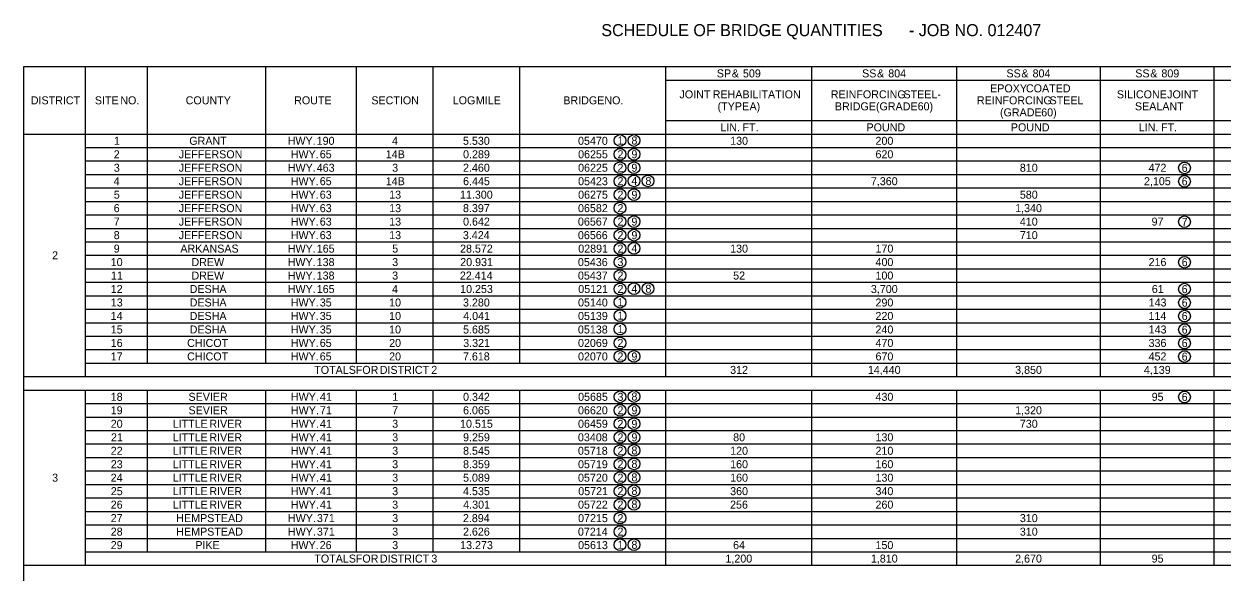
# Model space of a CAD drawing. Extents: x 16 to 1228740, y 11 to 152440.
# Drawn here: x 15.863 to 17.42, y 11.685 to 12.397 of the extents above; entities that cross this region are included whole.
import ezdxf

# ---------------------------------------------------------------- set-up
doc = ezdxf.new("R2010")
doc.units = 0
doc.layers.add('B_Text', color=7, linetype='Continuous')
doc.layers.add('Default', color=7, linetype='Continuous')

msp = doc.modelspace()

# ---------------------------------------------------------------- linework, layer by layer
at = {"layer": 'B_Text'}
msp.add_line((15.8634, 12.342), (15.8634, 12.342), dxfattribs=at)
for centre in [(16.6381, 12.246), (16.6563, 12.246), (16.6381, 12.2281), (16.6563, 12.2281), (16.6381, 12.2106), (16.6563, 12.2106), (17.3717, 12.2104), (16.6381, 12.1931), (16.6563, 12.1935), (16.6744, 12.1935), (17.3717, 12.1929), (16.6381, 12.1756), (16.6563, 12.1756), (16.6381, 12.1581), (16.6381, 12.1406), (16.6563, 12.1406), (17.3717, 12.1404), (16.6381, 12.123), (16.6563, 12.123), (16.6381, 12.1055), (16.6563, 12.1059), (16.6381, 12.088), (17.3717, 12.0878), (16.6381, 12.0705), (16.6381, 12.053), (16.6563, 12.0534), (16.6744, 12.0534), (17.3717, 12.0528), (16.6381, 12.0359), (17.3717, 12.0353), (16.6381, 12.0184), (17.3717, 12.0178), (16.6381, 12.0009), (17.3717, 12.0002), (16.6381, 11.9829), (17.3717, 11.9827), (16.6381, 11.9654), (16.6563, 11.9654), (17.3717, 11.9652), (16.6381, 11.9129), (16.6563, 11.9133), (17.3717, 11.9127), (16.6381, 11.8954), (16.6563, 11.8954), (16.6381, 11.8779), (16.6563, 11.8779), (16.6381, 11.8603), (16.6563, 11.8603), (16.6381, 11.8428), (16.6563, 11.8432), (16.6381, 11.8253), (16.6563, 11.8257), (16.6381, 11.8078), (16.6563, 11.8082), (16.6381, 11.7903), (16.6563, 11.7907), (16.6381, 11.7728), (16.6563, 11.7732), (16.6381, 11.7553), (16.6381, 11.7377), (16.6381, 11.7206), (16.6563, 11.7206)]:
    msp.add_circle(centre, 0.00762, dxfattribs=at)
at = {"layer": 'Default'}
for p, q in [((15.8634, 12.342), (17.9605, 12.342)), ((15.8634, 11.2211), (15.8634, 12.342)), ((15.9436, 11.9391), (15.9436, 12.342)), ((16.0238, 11.9567), (16.0238, 12.342)), ((16.1778, 11.9567), (16.1778, 12.342)), ((16.2958, 11.9567), (16.2958, 12.342)), ((16.3953, 11.9567), (16.3953, 12.342)), ((16.5078, 11.9567), (16.5078, 12.342)), ((16.6976, 11.9391), (16.6976, 12.342)), ((16.8875, 11.9391), (16.8875, 12.342)), ((17.0756, 11.9391), (17.0756, 12.342)), ((17.2627, 11.9391), (17.2627, 12.342)), ((17.4102, 11.9391), (17.4102, 12.342)), ((16.6976, 12.3244), (17.9605, 12.3244)), ((16.6976, 12.2719), (17.9605, 12.2719)), ((15.8634, 12.2544), (17.9605, 12.2544)), ((17.4102, 12.1668), (17.4102, 12.2544)), ((15.9436, 12.2369), (17.9605, 12.2369)), ((15.9436, 12.2194), (17.9605, 12.2194)), ((15.9436, 12.2019), (17.9605, 12.2019)), ((15.9436, 12.1843), (17.9605, 12.1843)), ((15.9436, 12.1668), (17.9605, 12.1668)), ((15.9436, 12.1493), (17.9605, 12.1493)), ((15.9436, 12.1318), (17.9605, 12.1318)), ((15.9436, 12.1143), (17.9605, 12.1143)), ((15.9436, 12.0968), (17.9605, 12.0968)), ((15.9436, 12.0793), (17.9605, 12.0793)), ((15.9436, 12.0617), (17.9605, 12.0617)), ((15.9436, 12.0442), (17.9605, 12.0442)), ((15.9436, 12.0267), (17.9605, 12.0267)), ((15.9436, 12.0092), (17.9605, 12.0092)), ((15.9436, 11.9917), (17.9605, 11.9917)), ((15.9436, 11.9742), (17.9605, 11.9742)), ((17.4102, 11.9567), (17.4102, 11.9742)), ((15.9436, 11.9567), (17.9605, 11.9567)), ((15.8634, 11.9391), (17.9605, 11.9391)), ((15.8634, 11.9216), (17.9605, 11.9216)), ((15.9436, 11.694), (15.9436, 11.9216)), ((16.0238, 11.7115), (16.0238, 11.9216)), ((16.1778, 11.7115), (16.1778, 11.9216)), ((16.2958, 11.7115), (16.2958, 11.9216)), ((16.3953, 11.7115), (16.3953, 11.9216)), ((16.5078, 11.7115), (16.5078, 11.9216)), ((16.6976, 11.694), (16.6976, 11.9216)), ((16.8875, 11.694), (16.8875, 11.9216)), ((17.0756, 11.694), (17.0756, 11.9216)), ((17.2627, 11.694), (17.2627, 11.9216)), ((17.4102, 11.694), (17.4102, 11.9216)), ((15.9436, 11.9041), (17.9605, 11.9041)), ((15.9436, 11.8866), (17.9605, 11.8866)), ((15.9436, 11.8691), (17.9605, 11.8691)), ((15.9436, 11.8516), (17.9605, 11.8516)), ((15.9436, 11.8341), (17.9605, 11.8341)), ((15.9436, 11.8166), (17.9605, 11.8166)), ((15.9436, 11.799), (17.9605, 11.799)), ((15.9436, 11.7815), (17.9605, 11.7815)), ((15.9436, 11.764), (17.9605, 11.764)), ((15.9436, 11.7465), (17.9605, 11.7465)), ((15.9436, 11.729), (17.9605, 11.729)), ((15.9436, 11.7115), (17.9605, 11.7115)), ((15.8634, 11.694), (17.9605, 11.694))]:
    msp.add_line(p, q, dxfattribs=at)

# ---------------------------------------------------------------- texts
at = {"layer": 'B_Text'}
for s, height, p in [('SCHEDULE OF BRIDGE QUANTITIES', 0.015625, (16.6138, 12.3816)), (' - JOB NO. 012407', 0.015625, (17.0078, 12.3816)), ('1', 0.0104, (16.6348, 12.2408)), ('8', 0.0104, (16.6529, 12.2408)), ('2', 0.0104, (16.6348, 12.2229)), ('9', 0.0104, (16.6529, 12.2229)), ('2', 0.0104, (16.6348, 12.2054)), ('9', 0.0104, (16.6529, 12.2054)), ('6', 0.0104, (17.368, 12.2052)), ('2', 0.0104, (16.6348, 12.1879)), ('4', 0.0104, (16.6529, 12.1883)), ('8', 0.0104, (16.6711, 12.1883)), ('6', 0.0104, (17.368, 12.1877)), ('2', 0.0104, (16.6348, 12.1704)), ('9', 0.0104, (16.6529, 12.1704)), ('2', 0.0104, (16.6348, 12.1529)), ('2', 0.0104, (16.6348, 12.1353)), ('9', 0.0104, (16.6529, 12.1353)), ('7', 0.0104, (17.368, 12.1351)), ('2', 0.0104, (16.6348, 12.1178)), ('9', 0.0104, (16.6529, 12.1178)), ('2', 0.0104, (16.6348, 12.1003)), ('4', 0.0104, (16.6529, 12.1007)), ('3', 0.0104, (16.6348, 12.0828)), ('6', 0.0104, (17.368, 12.0826)), ('2', 0.0104, (16.6348, 12.0653)), ('2', 0.0104, (16.6348, 12.0478)), ('4', 0.0104, (16.6529, 12.0482)), ('8', 0.0104, (16.6711, 12.0482)), ('6', 0.0104, (17.368, 12.0476)), ('1', 0.0104, (16.6348, 12.0307)), ('6', 0.0104, (17.368, 12.0301)), ('1', 0.0104, (16.6348, 12.0132)), ('6', 0.0104, (17.368, 12.0126)), ('1', 0.0104, (16.6348, 11.9957)), ('6', 0.0104, (17.368, 11.995)), ('2', 0.0104, (16.6348, 11.9777)), ('6', 0.0104, (17.368, 11.9775)), ('2', 0.0104, (16.6348, 11.9602)), ('9', 0.0104, (16.6529, 11.9602)), ('6', 0.0104, (17.368, 11.96)), ('3', 0.0104, (16.6348, 11.9077)), ('8', 0.0104, (16.6529, 11.9081)), ('6', 0.0104, (17.368, 11.9075)), ('2', 0.0104, (16.6348, 11.8902)), ('9', 0.0104, (16.6529, 11.8902)), ('2', 0.0104, (16.6348, 11.8726)), ('9', 0.0104, (16.6529, 11.8726)), ('2', 0.0104, (16.6348, 11.8551)), ('9', 0.0104, (16.6529, 11.8551)), ('2', 0.0104, (16.6348, 11.8376)), ('8', 0.0104, (16.6529, 11.838)), ('2', 0.0104, (16.6348, 11.8201)), ('8', 0.0104, (16.6529, 11.8205)), ('2', 0.0104, (16.6348, 11.8026)), ('8', 0.0104, (16.6529, 11.803)), ('2', 0.0104, (16.6348, 11.7851)), ('8', 0.0104, (16.6529, 11.7855)), ('2', 0.0104, (16.6348, 11.7676)), ('8', 0.0104, (16.6529, 11.768)), ('2', 0.0104, (16.6348, 11.75)), ('2', 0.0104, (16.6348, 11.7325)), ('1', 0.0104, (16.6348, 11.7154)), ('8', 0.0104, (16.6529, 11.7154))]:
    msp.add_text(s, height=height, dxfattribs=at).set_placement(p)
at = {"layer": 'Default'}
for s, height, p in [('SP', 0.0104, (16.7639, 12.328)), (' &', 0.0104, (16.7795, 12.328)), (' 509', 0.0104, (16.794, 12.328)), ('SS', 0.0104, (16.9527, 12.328)), (' &', 0.0104, (16.9683, 12.328)), (' 804', 0.0104, (16.9828, 12.328)), ('SS', 0.0104, (17.1403, 12.328)), (' &', 0.0104, (17.1559, 12.328)), (' 804', 0.0104, (17.1704, 12.328)), ('SS', 0.0104, (17.3077, 12.328)), (' &', 0.0104, (17.3233, 12.328)), (' 809', 0.0104, (17.3378, 12.328)), ('EPOXY', 0.0104, (17.1191, 12.3086)), (' COATED', 0.0104, (17.1618, 12.3086)), ('DISTRICT', 0.0104, (15.8723, 12.293)), ('SITE', 0.0104, (15.9556, 12.293)), (' NO.', 0.0104, (15.9848, 12.293)), ('COUNTY', 0.0104, (16.0736, 12.293)), ('ROUTE', 0.0104, (16.2146, 12.293)), ('SECTION', 0.0104, (16.3149, 12.293)), ('LOG', 0.0104, (16.4207, 12.293)), (' MILE', 0.0104, (16.4468, 12.293)), ('BRIDGE', 0.0104, (16.5644, 12.293)), (' NO.', 0.0104, (16.6139, 12.293)), ('JOINT', 0.0104, (16.7154, 12.3008)), (' REHABILITATION', 0.010399, (16.7547, 12.3008)), ('REINFORCING', 0.010399, (16.912, 12.3008)), (' STEEL-', 0.0104, (17.0026, 12.3008)), ('REINFORCING', 0.010399, (17.1019, 12.293)), (' STEEL', 0.0104, (17.1925, 12.293)), ('SILICONE', 0.0104, (17.2838, 12.3008)), (' JOINT', 0.0104, (17.3453, 12.3008)), ('(TYPE', 0.0104, (16.7649, 12.2852)), (' A)', 0.0104, (16.8025, 12.2852)), ('BRIDGE', 0.0104, (16.9173, 12.2852)), (' (GRADE', 0.0104, (16.9668, 12.2852)), (' 60)', 0.0104, (17.021, 12.2852)), ('(GRADE', 0.0104, (17.1319, 12.2774)), (' 60)', 0.0104, (17.1816, 12.2774)), ('SEALANT', 0.0104, (17.3073, 12.2852)), ('LIN.', 0.0104, (16.7685, 12.2579)), (' FT.', 0.0104, (16.7934, 12.2579)), ('POUND', 0.0104, (16.9584, 12.2579)), ('POUND', 0.0104, (17.146, 12.2579)), ('LIN.', 0.0104, (17.3123, 12.2579)), (' FT.', 0.0104, (17.3373, 12.2579)), ('1', 0.0104, (15.9804, 12.2404)), ('GRANT', 0.0104, (16.0783, 12.2404)), ('HWY.', 0.0104, (16.2062, 12.2404)), (' 190', 0.0104, (16.24, 12.2404)), ('4', 0.0104, (16.3418, 12.2404)), ('5.530', 0.0104, (16.434, 12.2404)), ('05470', 0.0104, (16.5835, 12.2404)), ('130', 0.0104, (16.7812, 12.2404)), ('200', 0.0104, (16.9701, 12.2404)), ('2', 0.0104, (15.9801, 12.2229)), ('JEFFERSON', 0.0104, (16.0646, 12.2229)), ('HWY.', 0.0104, (16.2102, 12.2229)), (' 65', 0.0104, (16.244, 12.2229)), ('14B', 0.0104, (16.3337, 12.2229)), ('0.289', 0.0104, (16.4341, 12.2229)), ('06255', 0.0104, (16.5836, 12.2229)), ('620', 0.0104, (16.9701, 12.2229)), ('3', 0.0104, (15.9802, 12.2054)), ('JEFFERSON', 0.0104, (16.0646, 12.2054)), ('HWY.', 0.0104, (16.2063, 12.2054)), (' 463', 0.0104, (16.2401, 12.2054)), ('3', 0.0104, (16.342, 12.2054)), ('2.460', 0.0104, (16.434, 12.2054)), ('06225', 0.0104, (16.5836, 12.2054)), ('810', 0.0104, (17.1577, 12.2054)), ('472', 0.0104, (17.325, 12.2054)), ('4', 0.0104, (15.98, 12.1879)), ('JEFFERSON', 0.0104, (16.0646, 12.1879)), ('HWY.', 0.0104, (16.2102, 12.1879)), (' 65', 0.0104, (16.244, 12.1879)), ('14B', 0.0104, (16.3337, 12.1879)), ('6.445', 0.0104, (16.4341, 12.1879)), ('05423', 0.0104, (16.5836, 12.1879)), ('7,360', 0.0104, (16.9641, 12.1879)), ('2,105', 0.0104, (17.319, 12.1879)), ('5', 0.0104, (15.9802, 12.1704)), ('JEFFERSON', 0.0104, (16.0646, 12.1704)), ('HWY.', 0.0104, (16.2102, 12.1704)), (' 63', 0.0104, (16.244, 12.1704)), ('13', 0.0104, (16.3381, 12.1704)), ('11.300', 0.0104, (16.4301, 12.1704)), ('06275', 0.0104, (16.5836, 12.1704)), ('580', 0.0104, (17.1577, 12.1704)), ('6', 0.0104, (15.9801, 12.1529)), ('JEFFERSON', 0.0104, (16.0646, 12.1529)), ('HWY.', 0.0104, (16.2102, 12.1529)), (' 63', 0.0104, (16.244, 12.1529)), ('13', 0.0104, (16.3381, 12.1529)), ('8.397', 0.0104, (16.434, 12.1529)), ('06582', 0.0104, (16.5835, 12.1529)), ('1,340', 0.0104, (17.1516, 12.1529)), ('7', 0.0104, (15.9801, 12.1354)), ('JEFFERSON', 0.0104, (16.0646, 12.1354)), ('HWY.', 0.0104, (16.2102, 12.1354)), (' 63', 0.0104, (16.244, 12.1354)), ('13', 0.0104, (16.3381, 12.1354)), ('0.642', 0.0104, (16.4341, 12.1354)), ('06567', 0.0104, (16.5834, 12.1354)), ('410', 0.0104, (17.1577, 12.1354)), ('97', 0.0104, (17.3289, 12.1354)), ('8', 0.0104, (15.9801, 12.1178)), ('JEFFERSON', 0.0104, (16.0646, 12.1178)), ('HWY.', 0.0104, (16.2102, 12.1178)), (' 63', 0.0104, (16.244, 12.1178)), ('13', 0.0104, (16.3381, 12.1178)), ('3.424', 0.0104, (16.4339, 12.1178)), ('06566', 0.0104, (16.5834, 12.1178)), ('710', 0.0104, (17.1577, 12.1178)), ('2', 0.0104, (15.9, 12.0916)), ('9', 0.0104, (15.9801, 12.1003)), ('ARKANSAS', 0.0104, (16.0667, 12.1003)), ('HWY.', 0.0104, (16.2063, 12.1003)), (' 165', 0.0104, (16.2401, 12.1003)), ('5', 0.0104, (16.342, 12.1003)), ('28.572', 0.0104, (16.4302, 12.1003)), ('02891', 0.0104, (16.5838, 12.1003)), ('130', 0.0104, (16.7812, 12.1003)), ('170', 0.0104, (16.9701, 12.1003)), ('10', 0.0104, (15.9762, 12.0828)), ('DREW', 0.0104, (16.0811, 12.0828)), ('HWY.', 0.0104, (16.2062, 12.0828)), (' 138', 0.0104, (16.24, 12.0828)), ('3', 0.0104, (16.342, 12.0828)), ('20.931', 0.0104, (16.4304, 12.0828)), ('05436', 0.0104, (16.5834, 12.0828)), ('400', 0.0104, (16.9701, 12.0828)), ('216', 0.0104, (17.325, 12.0828)), ('11', 0.0104, (15.9765, 12.0653)), ('DREW', 0.0104, (16.0811, 12.0653)), ('HWY.', 0.0104, (16.2062, 12.0653)), (' 138', 0.0104, (16.24, 12.0653)), ('3', 0.0104, (16.342, 12.0653)), ('22.414', 0.0104, (16.43, 12.0653)), ('05437', 0.0104, (16.5834, 12.0653)), ('52', 0.0104, (16.7851, 12.0653)), ('100', 0.0104, (16.9701, 12.0653)), ('12', 0.0104, (15.9762, 12.0478)), ('DESHA', 0.0104, (16.0788, 12.0478)), ('HWY.', 0.0104, (16.2063, 12.0478)), (' 165', 0.0104, (16.2401, 12.0478)), ('4', 0.0104, (16.3418, 12.0478)), ('10.253', 0.0104, (16.4303, 12.0478)), ('05121', 0.0104, (16.5838, 12.0478)), ('3,700', 0.0104, (16.9641, 12.0478)), ('61', 0.0104, (17.3292, 12.0478)), ('13', 0.0104, (15.9763, 12.0303)), ('DESHA', 0.0104, (16.0788, 12.0303)), ('HWY.', 0.0104, (16.2102, 12.0303)), (' 35', 0.0104, (16.244, 12.0303)), ('10', 0.0104, (16.338, 12.0303)), ('3.280', 0.0104, (16.434, 12.0303)), ('05140', 0.0104, (16.5835, 12.0303)), ('290', 0.0104, (16.9701, 12.0303)), ('143', 0.0104, (17.3251, 12.0303)), ('14', 0.0104, (15.9761, 12.0128)), ('DESHA', 0.0104, (16.0788, 12.0128)), ('HWY.', 0.0104, (16.2102, 12.0128)), (' 35', 0.0104, (16.244, 12.0128)), ('10', 0.0104, (16.338, 12.0128)), ('4.041', 0.0104, (16.4343, 12.0128)), ('05139', 0.0104, (16.5835, 12.0128)), ('220', 0.0104, (16.9701, 12.0128)), ('114', 0.0104, (17.3249, 12.0128)), ('15', 0.0104, (15.9763, 11.9952)), ('DESHA', 0.0104, (16.0788, 11.9952)), ('HWY.', 0.0104, (16.2102, 11.9952)), (' 35', 0.0104, (16.244, 11.9952)), ('10', 0.0104, (16.338, 11.9952)), ('5.685', 0.0104, (16.4341, 11.9952)), ('05138', 0.0104, (16.5834, 11.9952)), ('240', 0.0104, (16.9701, 11.9952)), ('143', 0.0104, (17.3251, 11.9952)), ('16', 0.0104, (15.9762, 11.9777)), ('CHICOT', 0.0104, (16.0755, 11.9777)), ('HWY.', 0.0104, (16.2102, 11.9777)), (' 65', 0.0104, (16.244, 11.9777)), ('20', 0.0104, (16.338, 11.9777)), ('3.321', 0.0104, (16.4343, 11.9777)), ('02069', 0.0104, (16.5835, 11.9777)), ('470', 0.0104, (16.9701, 11.9777)), ('336', 0.0104, (17.325, 11.9777)), ('17', 0.0104, (15.9762, 11.9602)), ('CHICOT', 0.0104, (16.0755, 11.9602)), ('HWY.', 0.0104, (16.2102, 11.9602)), (' 65', 0.0104, (16.244, 11.9602)), ('20', 0.0104, (16.338, 11.9602)), ('7.618', 0.0104, (16.434, 11.9602)), ('02070', 0.0104, (16.5835, 11.9602)), ('670', 0.0104, (16.9701, 11.9602)), ('452', 0.0104, (17.325, 11.9602)), ('TOTALS', 0.0104, (16.2407, 11.9427)), (' FOR', 0.0104, (16.2908, 11.9427)), (' DISTRICT', 0.0104, (16.322, 11.9427)), (' 2', 0.0104, (16.3889, 11.9427)), ('312', 0.0104, (16.7812, 11.9427)), ('14,440', 0.0104, (16.9602, 11.9427)), ('3,850', 0.0104, (17.1516, 11.9427)), ('4,139', 0.0104, (17.3189, 11.9427)), ('18', 0.0104, (15.9762, 11.9077)), ('SEVIER', 0.0104, (16.0773, 11.9077)), ('HWY.', 0.0104, (16.2104, 11.9077)), (' 41', 0.0104, (16.2442, 11.9077)), ('1', 0.0104, (16.3422, 11.9077)), ('0.342', 0.0104, (16.4341, 11.9077)), ('05685', 0.0104, (16.5836, 11.9077)), ('430', 0.0104, (16.9701, 11.9077)), ('95', 0.0104, (17.329, 11.9077)), ('19', 0.0104, (15.9762, 11.8902)), ('SEVIER', 0.0104, (16.0773, 11.8902)), ('HWY.', 0.0104, (16.2104, 11.8902)), (' 71', 0.0104, (16.2442, 11.8902)), ('7', 0.0104, (16.3419, 11.8902)), ('6.065', 0.0104, (16.4341, 11.8902)), ('06620', 0.0104, (16.5835, 11.8902)), ('1,320', 0.0104, (17.1516, 11.8902)), ('20', 0.0104, (15.9762, 11.8727)), ('LITTLE', 0.0104, (16.0567, 11.8727)), (' RIVER', 0.0104, (16.1005, 11.8727)), ('HWY.', 0.0104, (16.2104, 11.8727)), (' 41', 0.0104, (16.2442, 11.8727)), ('3', 0.0104, (16.342, 11.8727)), ('10.515', 0.0104, (16.4302, 11.8727)), ('06459', 0.0104, (16.5835, 11.8727)), ('730', 0.0104, (17.1577, 11.8727)), ('21', 0.0104, (15.9765, 11.8551)), ('LITTLE', 0.0104, (16.0567, 11.8551)), (' RIVER', 0.0104, (16.1005, 11.8551)), ('HWY.', 0.0104, (16.2104, 11.8551)), (' 41', 0.0104, (16.2442, 11.8551)), ('3', 0.0104, (16.342, 11.8551)), ('9.259', 0.0104, (16.4341, 11.8551)), ('03408', 0.0104, (16.5834, 11.8551)), ('80', 0.0104, (16.7851, 11.8551)), ('130', 0.0104, (16.9701, 11.8551)), ('22', 0.0104, (15.9762, 11.8376)), ('LITTLE', 0.0104, (16.0567, 11.8376)), (' RIVER', 0.0104, (16.1005, 11.8376)), ('HWY.', 0.0104, (16.2104, 11.8376)), (' 41', 0.0104, (16.2442, 11.8376)), ('3', 0.0104, (16.342, 11.8376)), ('8.545', 0.0104, (16.4341, 11.8376)), ('05718', 0.0104, (16.5834, 11.8376)), ('120', 0.0104, (16.7812, 11.8376)), ('210', 0.0104, (16.9701, 11.8376)), ('23', 0.0104, (15.9763, 11.8201)), ('LITTLE', 0.0104, (16.0567, 11.8201)), (' RIVER', 0.0104, (16.1005, 11.8201)), ('HWY.', 0.0104, (16.2104, 11.8201)), (' 41', 0.0104, (16.2442, 11.8201)), ('3', 0.0104, (16.342, 11.8201)), ('8.359', 0.0104, (16.4341, 11.8201)), ('05719', 0.0104, (16.5835, 11.8201)), ('160', 0.0104, (16.7812, 11.8201)), ('160', 0.0104, (16.9701, 11.8201)), ('3', 0.0104, (15.9, 11.8026)), ('24', 0.0104, (15.9761, 11.8026)), ('LITTLE', 0.0104, (16.0567, 11.8026)), (' RIVER', 0.0104, (16.1005, 11.8026)), ('HWY.', 0.0104, (16.2104, 11.8026)), (' 41', 0.0104, (16.2442, 11.8026)), ('3', 0.0104, (16.342, 11.8026)), ('5.089', 0.0104, (16.4341, 11.8026)), ('05720', 0.0104, (16.5835, 11.8026)), ('160', 0.0104, (16.7812, 11.8026)), ('130', 0.0104, (16.9701, 11.8026)), ('25', 0.0104, (15.9763, 11.7851)), ('LITTLE', 0.0104, (16.0567, 11.7851)), (' RIVER', 0.0104, (16.1005, 11.7851)), ('HWY.', 0.0104, (16.2104, 11.7851)), (' 41', 0.0104, (16.2442, 11.7851)), ('3', 0.0104, (16.342, 11.7851)), ('4.535', 0.0104, (16.4341, 11.7851)), ('05721', 0.0104, (16.5838, 11.7851)), ('360', 0.0104, (16.7812, 11.7851)), ('340', 0.0104, (16.9701, 11.7851)), ('26', 0.0104, (15.9762, 11.7676)), ('LITTLE', 0.0104, (16.0567, 11.7676)), (' RIVER', 0.0104, (16.1005, 11.7676)), ('HWY.', 0.0104, (16.2104, 11.7676)), (' 41', 0.0104, (16.2442, 11.7676)), ('3', 0.0104, (16.342, 11.7676)), ('4.301', 0.0104, (16.4343, 11.7676)), ('05722', 0.0104, (16.5835, 11.7676)), ('256', 0.0104, (16.7811, 11.7676)), ('260', 0.0104, (16.9701, 11.7676)), ('27', 0.0104, (15.9762, 11.7501)), ('HEMPSTEAD', 0.0104, (16.0614, 11.7501)), ('HWY.', 0.0104, (16.2065, 11.7501)), (' 371', 0.0104, (16.2403, 11.7501)), ('3', 0.0104, (16.342, 11.7501)), ('2.894', 0.0104, (16.4339, 11.7501)), ('07215', 0.0104, (16.5836, 11.7501)), ('310', 0.0104, (17.1577, 11.7501)), ('28', 0.0104, (15.9762, 11.7325)), ('HEMPSTEAD', 0.0104, (16.0614, 11.7325)), ('HWY.', 0.0104, (16.2065, 11.7325)), (' 371', 0.0104, (16.2403, 11.7325)), ('3', 0.0104, (16.342, 11.7325)), ('2.626', 0.0104, (16.434, 11.7325)), ('07214', 0.0104, (16.5834, 11.7325)), ('310', 0.0104, (17.1577, 11.7325)), ('29', 0.0104, (15.9762, 11.715)), ('PIKE', 0.0104, (16.0862, 11.715)), ('HWY.', 0.0104, (16.2101, 11.715)), (' 26', 0.0104, (16.2439, 11.715)), ('3', 0.0104, (16.342, 11.715)), ('13.273', 0.0104, (16.4303, 11.715)), ('05613', 0.0104, (16.5836, 11.715)), ('64', 0.0104, (16.785, 11.715)), ('150', 0.0104, (16.9701, 11.715)), ('TOTALS', 0.0104, (16.2408, 11.6975)), (' FOR', 0.0104, (16.2909, 11.6975)), (' DISTRICT', 0.0104, (16.3221, 11.6975)), (' 3', 0.0104, (16.389, 11.6975)), ('1,200', 0.0104, (16.7751, 11.6975)), ('1,810', 0.0104, (16.9641, 11.6975)), ('2,670', 0.0104, (17.1516, 11.6975)), ('95', 0.0104, (17.329, 11.6975))]:
    msp.add_text(s, height=height, dxfattribs=at).set_placement(p)

doc.saveas('drawing.dxf')
